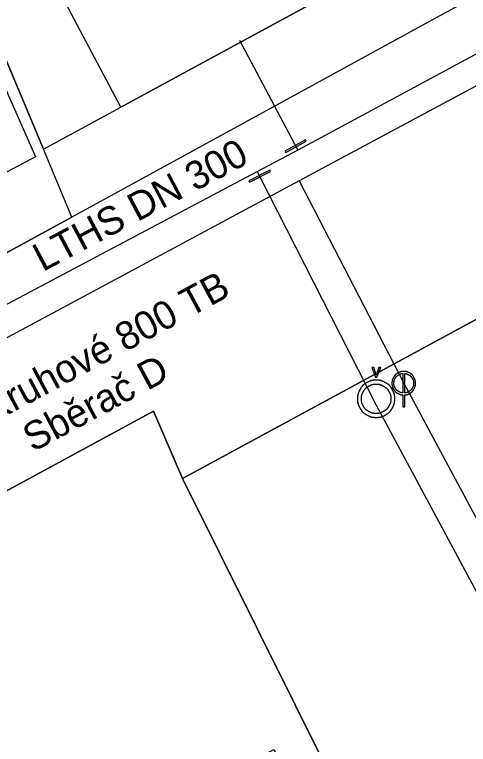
# Model space of a CAD drawing. Extents: x -562248 to -562040, y -1079385 to -1079027.
# Drawn here: x -562116.99 to -562092.87, y -1079306.51 to -1079267.68 of the extents above; entities that cross this region are included whole.
import ezdxf

# ---------------------------------------------------------------- set-up
doc = ezdxf.new("R2010")
doc.units = 0
for name, color, linetype in [('Armatura vodovodní', 7, 'Continuous'), ('Default', 7, 'Continuous'), ('Kanalizační přípojka', 7, 'Continuous'), ('Kanalizační stoka', 7, 'Continuous'), ('Kanalizační šachta', 7, 'Continuous'), ('Označení stoky', 7, 'Continuous'), ('Parcela-polygon', 7, 'Continuous'), ('Popis kmenové stoky', 7, 'Continuous'), ('Vodovodní přípojka', 7, 'Continuous'), ('Vodovodní řad', 7, 'Continuous'), ('Vodovodní šachta', 7, 'Continuous'), ('Řad vodovodní popis', 7, 'Continuous')]:
    doc.layers.add(name, color=color, linetype=linetype)

msp = doc.modelspace()

# ---------------------------------------------------------------- linework, layer by layer
at = {"layer": 'Armatura vodovodní'}
for points in [[(-562102.584, -1079275.013), (-562101.488, -1079274.411), (-562101.526, -1079274.342), (-562102.621, -1079274.944)], [(-562104.506, -1079276.603), (-562103.391, -1079276.036), (-562103.427, -1079275.967), (-562104.541, -1079276.533)]]:
    msp.add_lwpolyline(points, close=True, dxfattribs=at)
at = {"layer": 'Default'}
for points in [[(-562097.768, -1079286.857), (-562097.771, -1079286.839), (-562097.774, -1079286.827), (-562097.779, -1079286.823)], [(-562097.755, -1079286.823), (-562097.759, -1079286.832), (-562097.764, -1079286.843), (-562097.768, -1079286.857)], [(-562096.852, -1079286.981), (-562096.908, -1079287.082), (-562096.936, -1079287.186), (-562096.936, -1079287.295)], [(-562096.619, -1079286.751), (-562096.718, -1079286.804), (-562096.796, -1079286.881), (-562096.852, -1079286.981)], [(-562096.762, -1079287.034), (-562096.716, -1079286.951), (-562096.651, -1079286.887), (-562096.568, -1079286.841)], [(-562096.311, -1079286.67), (-562096.417, -1079286.67), (-562096.52, -1079286.697), (-562096.619, -1079286.751)], [(-562096.568, -1079286.841), (-562096.496, -1079286.804), (-562096.428, -1079286.782), (-562096.363, -1079286.775)], [(-562096.004, -1079286.751), (-562096.103, -1079286.697), (-562096.206, -1079286.67), (-562096.311, -1079286.67)], [(-562096.26, -1079286.775), (-562096.193, -1079286.782), (-562096.125, -1079286.804), (-562096.055, -1079286.841)], [(-562096.055, -1079286.841), (-562095.972, -1079286.887), (-562095.907, -1079286.951), (-562095.86, -1079287.034)], [(-562095.771, -1079286.981), (-562095.827, -1079286.881), (-562095.905, -1079286.804), (-562096.004, -1079286.751)], [(-562095.686, -1079287.295), (-562095.686, -1079287.186), (-562095.715, -1079287.082), (-562095.771, -1079286.981)], [(-562098.264, -1079287.26), (-562098.421, -1079287.345), (-562098.544, -1079287.467), (-562098.633, -1079287.626)], [(-562097.779, -1079287.134), (-562097.945, -1079287.134), (-562098.107, -1079287.176), (-562098.264, -1079287.26)], [(-562098.16, -1079287.443), (-562098.036, -1079287.376), (-562097.909, -1079287.342), (-562097.779, -1079287.342)], [(-562097.292, -1079287.26), (-562097.45, -1079287.176), (-562097.612, -1079287.134), (-562097.779, -1079287.134)], [(-562097.779, -1079287.342), (-562097.646, -1079287.342), (-562097.518, -1079287.376), (-562097.394, -1079287.443)], [(-562096.921, -1079287.626), (-562097.01, -1079287.467), (-562097.133, -1079287.345), (-562097.292, -1079287.26)], [(-562096.936, -1079287.295), (-562096.936, -1079287.403), (-562096.909, -1079287.506), (-562096.853, -1079287.605)], [(-562096.831, -1079287.295), (-562096.831, -1079287.204), (-562096.808, -1079287.117), (-562096.762, -1079287.034)], [(-562096.763, -1079287.553), (-562096.809, -1079287.471), (-562096.831, -1079287.385), (-562096.831, -1079287.295)], [(-562095.86, -1079287.034), (-562095.813, -1079287.117), (-562095.789, -1079287.204), (-562095.789, -1079287.295)], [(-562095.789, -1079287.295), (-562095.789, -1079287.385), (-562095.812, -1079287.471), (-562095.857, -1079287.553)], [(-562095.768, -1079287.605), (-562095.714, -1079287.506), (-562095.686, -1079287.403), (-562095.686, -1079287.295)], [(-562098.633, -1079287.626), (-562098.722, -1079287.786), (-562098.766, -1079287.952), (-562098.766, -1079288.125)], [(-562098.558, -1079288.125), (-562098.558, -1079287.988), (-562098.523, -1079287.857), (-562098.452, -1079287.732)], [(-562098.452, -1079287.732), (-562098.381, -1079287.607), (-562098.284, -1079287.51), (-562098.16, -1079287.443)], [(-562097.394, -1079287.443), (-562097.27, -1079287.51), (-562097.173, -1079287.607), (-562097.102, -1079287.732)], [(-562097.102, -1079287.732), (-562097.031, -1079287.857), (-562096.996, -1079287.988), (-562096.996, -1079288.125)], [(-562096.787, -1079288.125), (-562096.787, -1079287.952), (-562096.832, -1079287.786), (-562096.921, -1079287.626)], [(-562096.853, -1079287.605), (-562096.798, -1079287.705), (-562096.721, -1079287.782), (-562096.622, -1079287.837)], [(-562096.57, -1079287.744), (-562096.653, -1079287.699), (-562096.718, -1079287.635), (-562096.763, -1079287.553)], [(-562096.363, -1079287.813), (-562096.431, -1079287.808), (-562096.5, -1079287.785), (-562096.57, -1079287.744)], [(-562096.05, -1079287.744), (-562096.122, -1079287.785), (-562096.192, -1079287.808), (-562096.26, -1079287.813)], [(-562095.857, -1079287.553), (-562095.903, -1079287.635), (-562095.967, -1079287.699), (-562096.05, -1079287.744)], [(-562095.999, -1079287.837), (-562095.9, -1079287.782), (-562095.823, -1079287.705), (-562095.768, -1079287.605)], [(-562098.766, -1079288.125), (-562098.766, -1079288.296), (-562098.723, -1079288.459), (-562098.635, -1079288.616)], [(-562098.454, -1079288.511), (-562098.523, -1079288.388), (-562098.558, -1079288.26), (-562098.558, -1079288.125)], [(-562096.996, -1079288.125), (-562096.996, -1079288.26), (-562097.031, -1079288.388), (-562097.1, -1079288.511)], [(-562096.917, -1079288.616), (-562096.831, -1079288.459), (-562096.787, -1079288.296), (-562096.787, -1079288.125)], [(-562096.622, -1079287.837), (-562096.535, -1079287.886), (-562096.449, -1079287.913), (-562096.363, -1079287.918)], [(-562096.26, -1079287.918), (-562096.174, -1079287.913), (-562096.087, -1079287.886), (-562095.999, -1079287.837)], [(-562098.165, -1079288.798), (-562098.288, -1079288.73), (-562098.384, -1079288.634), (-562098.454, -1079288.511)], [(-562097.1, -1079288.511), (-562097.17, -1079288.634), (-562097.266, -1079288.73), (-562097.389, -1079288.798)], [(-562098.635, -1079288.616), (-562098.547, -1079288.772), (-562098.425, -1079288.894), (-562098.267, -1079288.981)], [(-562097.779, -1079288.901), (-562097.913, -1079288.901), (-562098.042, -1079288.867), (-562098.165, -1079288.798)], [(-562097.389, -1079288.798), (-562097.512, -1079288.867), (-562097.642, -1079288.901), (-562097.779, -1079288.901)], [(-562097.283, -1079288.981), (-562097.126, -1079288.894), (-562097.004, -1079288.772), (-562096.917, -1079288.616)], [(-562098.267, -1079288.981), (-562098.11, -1079289.069), (-562097.947, -1079289.113), (-562097.779, -1079289.113)], [(-562097.779, -1079289.113), (-562097.605, -1079289.113), (-562097.44, -1079289.069), (-562097.283, -1079288.981)]]:
    msp.add_open_spline(points, degree=2, dxfattribs=at)
at = {"layer": 'Kanalizační přípojka'}
for points in [[(-562101.861, -1079276.526), (-562096.311, -1079287.295)], [(-562096.311, -1079287.295), (-562086.67, -1079305.266)]]:
    msp.add_lwpolyline(points, dxfattribs=at)
at = {"layer": 'Kanalizační stoka'}
msp.add_lwpolyline([(-562077.25, -1079263.3), (-562101.861, -1079276.526), (-562138.86, -1079296.41)], dxfattribs=at)
at = {"layer": 'Kanalizační šachta'}
for points in [[(-562096.363, -1079286.775), (-562096.363, -1079287.813)], [(-562096.26, -1079287.813), (-562096.26, -1079286.775)], [(-562096.363, -1079288.545), (-562096.26, -1079288.545), (-562096.26, -1079287.918)], [(-562096.363, -1079287.918), (-562096.363, -1079288.545)]]:
    msp.add_lwpolyline(points, dxfattribs=at)
at = {"layer": 'Parcela-polygon'}
for points in [[(-562125.839, -1079250.062), (-562115.46, -1079274.84), (-562111.34, -1079272.6), (-562115.82, -1079264.13), (-562111.86, -1079261.96), (-562112.48, -1079260.84), (-562109.81, -1079259.38), (-562109.2, -1079260.5), (-562101.14, -1079256.08), (-562102.73, -1079253.17), (-562100.18, -1079251.98), (-562102.28, -1079247.51), (-562108.03, -1079234.16), (-562113.76, -1079220.84), (-562114.87, -1079218.31), (-562116.77, -1079219.12), (-562123.59, -1079221.97), (-562126.807, -1079223.131)], [(-562092.25, -1079234.14), (-562087.93, -1079243.96), (-562082.03, -1079256.6), (-562081.77, -1079257.15), (-562081.58, -1079257.9), (-562081.53, -1079258.52), (-562081.58, -1079259.09), (-562081.83, -1079259.97), (-562082.29, -1079260.79), (-562083.07, -1079261.58), (-562094.62, -1079267.87), (-562113.94, -1079278.46), (-562115.46, -1079274.84), (-562111.34, -1079272.6), (-562096.55, -1079264.55), (-562101.14, -1079256.08), (-562102.73, -1079253.17), (-562100.18, -1079251.98), (-562102.28, -1079247.51), (-562093.4, -1079243.66), (-562099.13, -1079230.34)], [(-562050.734, -1079242.89), (-562074.7, -1079253.09), (-562082.29, -1079260.79), (-562083.07, -1079261.58), (-562094.62, -1079267.87), (-562113.94, -1079278.46), (-562131.57, -1079288.07), (-562135.96, -1079290.46), (-562143.99, -1079294.84), (-562166.66, -1079307.21), (-562184.27, -1079316.57), (-562201.76, -1079326), (-562209.06, -1079330.03), (-562233.192, -1079343.166)], [(-562150.955, -1079262.816), (-562144.68, -1079274.39), (-562135.96, -1079290.46), (-562131.57, -1079288.07), (-562113.94, -1079278.46), (-562115.46, -1079274.84), (-562125.839, -1079250.062)], [(-562128.35, -1079262.95), (-562129.18, -1079261.41), (-562128.95, -1079260.62), (-562129.48, -1079259.64), (-562133.24, -1079261.69), (-562134.9, -1079261.17), (-562136.63, -1079257.94), (-562126.97, -1079252.69), (-562121.01, -1079263.69), (-562121.23, -1079263.8), (-562119.71, -1079266.58), (-562115.88, -1079275.25), (-562118.9, -1079276.84), (-562119.32, -1079277.09), (-562119.43, -1079276.92), (-562128.39, -1079281.65), (-562132.65, -1079273.7), (-562132.78, -1079273.77), (-562133, -1079273.36), (-562124.5, -1079268.83), (-562127.56, -1079263.19), (-562128.35, -1079262.95)], [(-562231.237, -1079347.297), (-562217.17, -1079339.57), (-562199.49, -1079329.98), (-562196.37, -1079335.83), (-562192.03, -1079333.48), (-562171.25, -1079322.22), (-562167.46, -1079320.16), (-562158.91, -1079315.52), (-562136.96, -1079303.61), (-562123.37, -1079296.24), (-562109.61, -1079288.78), (-562108.06, -1079292.36), (-562077.04, -1079275.54), (-562045.434, -1079258.412)], [(-562068.437, -1079293.845), (-562077.04, -1079275.54), (-562108.06, -1079292.36), (-562098.09, -1079312.42)], [(-562098.09, -1079312.42), (-562108.06, -1079292.36), (-562109.61, -1079288.78), (-562123.37, -1079296.24), (-562136.96, -1079303.61), (-562158.91, -1079315.52), (-562167.46, -1079320.16), (-562171.25, -1079322.22), (-562162.29, -1079338.64), (-562157.03, -1079335.76), (-562146.49, -1079329.95), (-562141.95, -1079327.52), (-562136.58, -1079324.65), (-562135.92, -1079324.29), (-562132.83, -1079322.64), (-562130.32, -1079321.29), (-562116.03, -1079313.64), (-562103.22, -1079306.78), (-562099.68, -1079313.416)]]:
    msp.add_lwpolyline(points, dxfattribs=at)
for points in [[(-562129.18, -1079261.41), (-562128.95, -1079260.62), (-562129.48, -1079259.64), (-562133.24, -1079261.69), (-562134.9, -1079261.17), (-562136.63, -1079257.94), (-562126.97, -1079252.69), (-562121.01, -1079263.69), (-562121.23, -1079263.8), (-562119.71, -1079266.58), (-562115.88, -1079275.25), (-562118.9, -1079276.84), (-562123.54, -1079268.32), (-562124.5, -1079268.83), (-562127.56, -1079263.19), (-562128.35, -1079262.95)], [(-562112.48, -1079260.84), (-562109.81, -1079259.38), (-562109.2, -1079260.5), (-562101.14, -1079256.08), (-562096.55, -1079264.55), (-562111.34, -1079272.6), (-562115.82, -1079264.13), (-562111.86, -1079261.96)]]:
    msp.add_lwpolyline(points, close=True, dxfattribs=at)
at = {"layer": 'Vodovodní přípojka'}
for points in [[(-562101.945, -1079274.886), (-562105.013, -1079269.056)], [(-562104.098, -1079276.026), (-562103.967, -1079276.284), (-562097.776, -1079288.457), (-562088.227, -1079306.241)]]:
    msp.add_lwpolyline(points, dxfattribs=at)
at = {"layer": 'Vodovodní řad'}
msp.add_lwpolyline([(-562205.614, -1079330.519), (-562174.097, -1079314.233), (-562147.992, -1079299.695), (-562146.568, -1079298.894), (-562118.26, -1079283.525), (-562104.098, -1079276.026), (-562101.887, -1079274.855), (-562091.855, -1079269.457), (-562077.721, -1079261.793), (-562076.873, -1079261.222)], dxfattribs=at)
at = {"layer": 'Vodovodní šachta'}
for points in [[(-562097.779, -1079286.823), (-562097.902, -1079286.464), (-562097.997, -1079286.464), (-562097.803, -1079286.966)], [(-562097.803, -1079286.966), (-562097.734, -1079286.966), (-562097.536, -1079286.464), (-562097.625, -1079286.464), (-562097.755, -1079286.823)]]:
    msp.add_lwpolyline(points, dxfattribs=at)

# ---------------------------------------------------------------- texts
at = {"layer": 'Označení stoky'}
msp.add_text('Sběrač D', height=1.5, rotation=28.2542, dxfattribs=at).set_placement((-562116.025, -1079290.98))
at = {"layer": 'Popis kmenové stoky'}
msp.add_text('Kruhové 800 TB', height=1.5, rotation=28.2542, dxfattribs=at).set_placement((-562118.194, -1079289.45))
at = {"layer": 'Řad vodovodní popis'}
msp.add_text('LTHS DN 300', height=1.5, rotation=27.9015, dxfattribs=at).set_placement((-562115.491, -1079281.385))

doc.saveas('drawing.dxf')
